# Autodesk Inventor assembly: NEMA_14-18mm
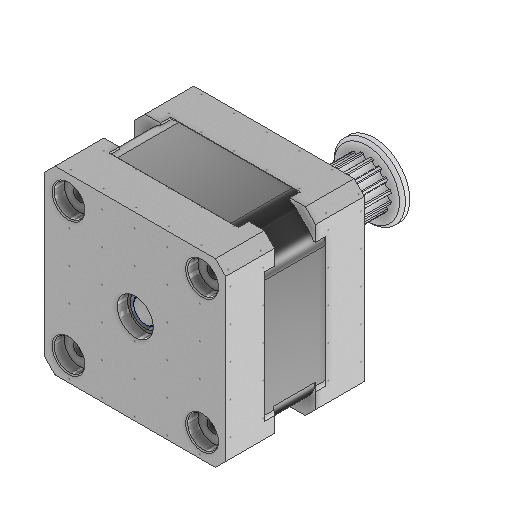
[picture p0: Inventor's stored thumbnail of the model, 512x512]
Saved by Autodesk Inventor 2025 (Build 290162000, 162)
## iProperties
Created: 2019-11
Part Number: NEMA_14-18mm
Material: Générique
Document SubType Name: Assembly
Designer: thoma
Author: thoma
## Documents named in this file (4)
- C:\Users\R5800u\Desktop\nema14\NEMA_14-18mm.iam
- C:\Users\R5800u\Desktop\nema14\NEMA_14HM11-0404S_BODY.ipt
- C:\Users\R5800u\Desktop\nema14\NEMA_14HM11-0404S_SHAFT.ipt
- C:\Users\R5800u\Desktop\nema14\GT2 16 Teeth Free Pulley.ipt
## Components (3 placed, 3 different names)
1. NEMA_14HM11-0404S:1 — Affleurement:2, Placage:2, Placage:3, Affleurement:3
2. NEMA_14HM11-0404S_SHAFT:1 — Affleurement:3, Rotazionale:1
3. GT2 16 Teeth Free Pulley:1 — Rotazionale:1
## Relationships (5: Flush 2, Mate 2, RevoluteJoint 1)
- Affleurement:2 [Flush]: NEMA_14HM11-0404S:1
- Placage:2 [Mate]: NEMA_14HM11-0404S:1
- Placage:3 [Mate]: NEMA_14HM11-0404S:1
- Affleurement:3 [Flush]: NEMA_14HM11-0404S:1 ↔ NEMA_14HM11-0404S_SHAFT:1
- Rotazionale:1 [RevoluteJoint]: NEMA_14HM11-0404S_SHAFT:1 ↔ GT2 16 Teeth Free Pulley:1
